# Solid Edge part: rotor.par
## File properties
Author: Argu
Template: Iso Part.par
Last saved by: Argu
Revision: 31
Application: Solid Edge
Accuracy: 0,990
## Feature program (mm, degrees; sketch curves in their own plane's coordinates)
sketch for "unnamed RevolvedProtrusion 1" plane through (0, 0, 0) normal (0, 0, 1) x-axis (1, 0, 0)
  line (0, 0) -> (0, -42)
  arc centre (273.2344, 17.3961) radius 291.9187 from (-17.975, -2.9408) to (-14.9255, -29.2984) ccw
  line (-18.1804, 0) -> (-17.975, -2.9408)
  line (0, 0) -> (-18.1804, 0)
revolve "unnamed RevolvedProtrusion 1" add finite 360 deg
sketch for "unnamed Protrusion 1" plane through (0, 0, 0) normal (0, 0, 1) x-axis (1, 0, 0)
  circle centre (0, -22) radius 5
extrude "unnamed Protrusion 1" add finite 20 along +normal
pattern "unnamed Pattern 1" of "unnamed Protrusion 1"
extrude "unnamed Protrusion 2" add finite 20
extrude "unnamed Protrusion 3" add finite 20
lofted protrusion "unnamed LoftedProtrusion 1"
lofted protrusion "unnamed LoftedProtrusion 2"
sketch for "unnamed RevolvedProtrusion 2" plane through (0, -12.7188, 228) normal (0, 0, 1) x-axis (-1, 0, 0)
  line (0, 10.7812) -> (0, -10.7865)
  arc centre (0, -9.778) radius 1.0085 from (0, -10.7865) to (1.0072, -9.83) ccw
  arc centre (-369.3093, 9.2812) radius 370.8093 from (1.0072, -9.83) to (1.5, 9.2812) ccw
  arc centre (0, 9.2812) radius 1.5 from (1.5, 9.2812) to (0, 10.7812) ccw
revolve "unnamed RevolvedProtrusion 2" add to key point
pattern "unnamed Pattern 2" of "unnamed LoftedProtrusion 2", "unnamed LoftedProtrusion 1", "unnamed RevolvedProtrusion 2"
lofted protrusion "unnamed LoftedProtrusion 3"
lofted protrusion "unnamed LoftedProtrusion 4"
revolve "unnamed RevolvedProtrusion 3" add finite 180 deg
lofted protrusion "unnamed LoftedProtrusion 5"
lofted protrusion "unnamed LoftedProtrusion 6"
revolve "unnamed RevolvedProtrusion 4" add finite 180 deg
sketch used by "ExtrudedProtrusion_5" plane through (0, 0, 0) normal (0, -1, 0) x-axis (1, 0, 0)
extrude "ExtrudedProtrusion_5" add finite 25 along -normal
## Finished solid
Body 1: solid body, 33 faces, 89 edges, 60 vertices.
  Faces by surface: spline 12, sphere 7, plane 5, cylinder 4, torus 4, cone 1
  Edges by curve: circle 56, curve on surface 18, spline 12, intersection 3
Bounding box of the edges (mm; curved faces can reach further): 397.908 x 54.298 x 345.000, from (-198.9538, -29.2984, -115.5) to (198.9538, 25, 229.5).
Cylindrical faces by radius (mm): R5 x4
Conical faces (half-angle, radius in mm at the cone's reference point): 3.9948 deg R17.975 x1
Toroidal faces (ring radius, tube radius in mm): R-369.3093 r370.8093 x3, R-273.2344 r291.9187 x1
Spherical faces by radius (mm): R1.0085 x3, R1.5 x3, R15.1202 x1
Planar faces by outward normal: +y 2, -z 1, oblique 2
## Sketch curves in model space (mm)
line (0, -23.5, 228) -> (0, -1.9323, 228)
arc centre (0, -2.9408, 228) radius 1.0085 from (0, -1.9323, 228) through (-0.6945, -2.2096, 228) to (-1.0072, -2.8889, 228)
arc centre (369.3093, -22, 228) radius 370.8093 from (-1.0072, -2.8889, 228) through (-1.3768, -12.4413, 228) to (-1.5, -22, 228)
arc centre (0, -22, 228) radius 1.5 from (-1.5, -22, 228) through (-1.0294, -23.0911, 228) to (0, -23.5, 228)
arc centre (0, -22, 100) radius 4.5 from (3.1962, -18.8323, 100) through (2.4288, -25.7883, 100) to (-3.9954, -24.0704, 100)
arc centre (59.9639, 37.4283, 100) radius 79.9239 from (-9.2272, -2.5769, 100) through (-3.5378, -11.1038, 100) to (3.1962, -18.8323, 100)
arc centre (-10.1586, -2.9408, 100) radius 1 from (-11.0755, -3.34, 100) through (-10.5124, -2.0055, 100) to (-9.2272, -2.5769, 100)
arc centre (61.5204, 9.8796, 100) radius 73.7898 from (-11.0755, -3.34, 100) through (-8.309, -13.9694, 100) to (-3.9954, -24.0704, 100)
arc centre (0, -2.9408, 228) radius 1.0085 from (-1.0072, -2.8889, 228) through (0.0858, -1.936, 228) to (1.0085, -2.9408, 228)
arc centre (-368.3008, -22, 228) radius 369.8008 from (1.5, -22, 228) through (1.3771, -12.4673, 228) to (1.0085, -2.9408, 228)
arc centre (0, -22, 228) radius 1.5 from (1.5, -22, 228) through (-0.0444, -23.4993, 228) to (-1.5, -22, 228)
arc centre (369.3093, -22, 228) radius 370.8093 from (-1.5, -22, 228) through (-1.3768, -12.4413, 228) to (-1.0072, -2.8889, 228)
arc centre (0, -22, 165) radius 3.5 from (3.0986, -20.3726, 165) through (1.2395, -25.2732, 165) to (-3.3439, -23.0336, 165)
arc centre (106.742, 34.0619, 165) radius 117.0686 from (-4.4288, -2.6274, 165) through (-1.0309, -11.6552, 165) to (3.0986, -20.3726, 165)
arc centre (-5.3785, -2.9408, 165) radius 1 from (-6.3785, -2.9408, 165) through (-5.5372, -1.9535, 165) to (-4.4288, -2.6274, 165)
arc centre (61.6591, -2.9408, 165) radius 68.0375 from (-6.3785, -2.9408, 165) through (-5.6155, -13.1012, 165) to (-3.3439, -23.0336, 165)
circle centre (-15.9374, -2.9408, 50) radius 0.0376
arc centre (0, -22, 50) radius 5.5 from (3.1395, -17.4841, 50) through (3.7721, -26.0026, 50) to (-4.5159, -25.1395, 50)
arc centre (54.4725, 56.3548, 50) radius 89.9291 from (-13.4728, -2.5578, 50) through (-5.6318, -10.5386, 50) to (3.1395, -17.4841, 50)
arc centre (-14.3965, -2.9408, 50) radius 1 from (-15.2759, -3.417, 50) through (-14.7727, -2.0143, 50) to (-13.4728, -2.5578, 50)
arc centre (63.1582, 21.9082, 50) radius 82.4213 from (-15.2759, -3.417, 50) through (-10.6989, -14.676, 50) to (-4.5159, -25.1395, 50)
circle centre (0, 0, 0) radius 5
arc centre (0, -22.1502, 20) radius 6 from (3.0761, -16.9988, 20) through (4.3342, -26.2993, 20) to (-4.5825, -26.0233, 20)
arc centre (84.8898, 49.5983, 20) radius 117.1492 from (-19.4725, -3.6223, 20) through (-12.6725, -15.2516, 20) to (-4.5825, -26.0233, 20)
arc centre (-18.1362, -2.9408, 20) radius 1.5 from (-19.4725, -3.6223, 20) through (-18.8787, -1.6375, 20) to (-16.9733, -1.9934, 20)
arc centre (64.8117, 86.3865, 20) radius 120.4151 from (-16.9733, -1.9934, 20) through (-7.3397, -10.0187, 20) to (3.0761, -16.9988, 20)
circle centre (0, -22, 0) radius 5
line (0, -9.2129, 0) -> (0, -34.7626, 0)
arc centre (0, -26.8798, 0) radius 15.1202 from (0, -42, 0) through (-9.7992, -38.3948, 0) to (-14.9255, -29.2984, 0)
arc centre (273.2344, 17.3961, 0) radius 291.9187 from (-17.975, -2.9408, 0) through (-16.7499, -16.1543, 0) to (-14.9255, -29.2984, 0)
line (-18.1804, 0, 0) -> (-17.975, -2.9408, 0)
line (0, 0, 0) -> (-18.1804, 0, 0)
line (0, 0, 0) -> (0, -42, 0)
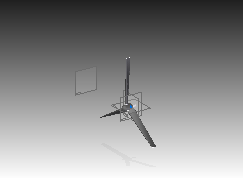
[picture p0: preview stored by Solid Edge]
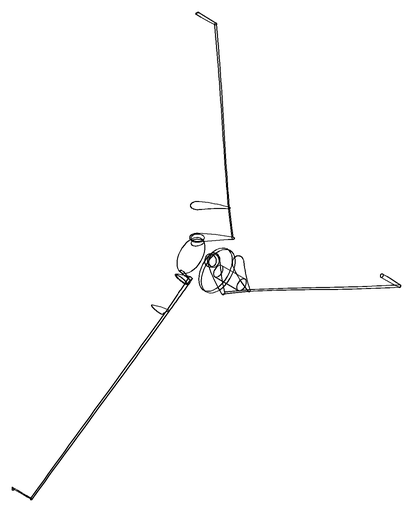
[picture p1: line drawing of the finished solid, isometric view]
